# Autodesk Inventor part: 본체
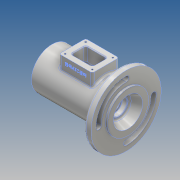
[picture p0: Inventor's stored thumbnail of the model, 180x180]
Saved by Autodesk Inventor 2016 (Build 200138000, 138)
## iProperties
Created: 2017-05
Part Number: 본체
Material: 알루미늄 6061
Document SubType Name: Modeling
Designer: Administrator
Density: 2.7 g/cm^3
Appearance: 알루미늄 - 평지
Mass: 677.521 g
Surface Area: 616.973 cm^2
Volume: 250.934 cm^3
Author: Administrator
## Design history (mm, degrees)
sketch "스케치2"
  geometry: L1 (-56, 0)-(59, 0); L2 (-56, 0)-(-56, 31); L3 (-56, 31)-(46, 31); L4 (46, 31)-(46, 53); L5 (46, 53)-(56, 53); L6 (56, 53)-(56, 31); L7 (56, 31)-(59, 31); L8 (59, 31)-(59, 0); 1 further point
  constraints: 16 end point, 5 perpendicular, 3 point on line, 1 horizontal, 1 vertical
  dimensions: "d1" = 115 distance of L1.start L1.end; "d2" = 3 distance between parallel lines of L6 L8; "d3" = 13 distance between parallel lines of L4 L8; "d4" = 106 diameter of L5 L1; "d5" = 62 diameter of L3 L1; "d6" = 56 distance from line of point (0, 0) L2
revolve "회전1" sketch "스케치2" stored, may be unused: angle "d7" = 90 deg
sketch "스케치3"
  geometry: L1 (-25, 20)-(25, 20); L2 (25, 20)-(25, -20); L3 (25, -20)-(-25, -20); L4 (-25, -20)-(-25, 20); L5 (-25, 20)-(25, -20); L6 (25, 20)-(-25, -20); 1 further point
  constraints: 12 end point, 2 midpoint, 2 parallel, 1 horizontal, 1 perpendicular
  dimensions: "d8" = 50 distance between parallel lines of L2 L4; "d9" = 40 distance between parallel lines of L3 L1
extrude "돌출1" join sketch "스케치3" distance "d10" = 44; taper "d11" = 0 deg
sketch "스케치5"
  geometry: L1 (-56, -31)-(-56, 31) reference; L2 (-56, 0)-(59, 0); L3 (59, -31)-(59, 31) reference; L4 (-56, 0)-(-56, 21); L5 (-56, 21)-(-47, 21); L6 (-47, 21)-(-47, 24); L7 (-47, 24)-(-44, 24); L8 (-44, 24)-(-44, 20); L9 (-44, 20)-(-35, 20); L10 (-35, 20)-(-35, 17.5); L11 (-35, 17.5)-(-31.75, 17.5); L12 (-31.75, 17.5)-(-31.75, 18.5); L13 (-31.75, 18.5)-(-30, 18.5); L14 (-30, 18.5)-(-30, 17.5); L15 (-30, 17.5)-(-19, 17.5); L16 (-19, 17.5)-(-19, 26); L17 (-19, 26)-(19, 26); L18 (19, 26)-(19, 17.5); L19 (19, 17.5)-(30, 17.5); L20 (30, 17.5)-(30, 16.5); L21 (30, 16.5)-(35, 16.5); L22 (35, 16.5)-(35, 10); L23 (35, 10)-(37.7, 10); L24 (37.7, 10)-(37.7, 12.5); L25 (37.7, 12.5)-(44.3, 12.5); L26 (46, -53)-(46, 53) reference; L27 (44.3, 12.5)-(45, 12.904); L28 (45, 12.904)-(45, 16); L29 (45, 16)-(59, 22); L30 (59, 22)-(59, 0); 2 further points
  constraints: 54 end point, 17 perpendicular, 4 point on line, 3 midpoint, 2 collinear, 2 vertical, 1 horizontal, 1 parallel, 1 vertical alignment
  dimensions: "d14" = 42 diameter of L5 L2; "d15" = 48 diameter of L7 L2; "d16" = 40 diameter of L9 L2; "d17" = 35 diameter of L11 L2; "d18" = 3 distance between parallel lines of L8 L6; "d19" = 12 distance between parallel lines of L8 L1; "d20" = 21 distance between parallel lines of L10 L1; "d21" = 37 diameter of L13 L2; "d22" = 1.75 distance from line of L14 L12.end; "d23" = 26 distance between parallel lines of L14 L4; "d24" = 11 distance between parallel lines of L16 L14; "d25" = 11 distance from line of L19.end L18; "d26" = 52 diameter of L17 L2; "d29" = 5 distance between parallel lines of L22 L20; "d31" = 2.7 distance between parallel lines of L24 L22; "d33" = 0.7 horizontal distance of L25.end L27.end; "d34" = 30 deg angle of L25 L27; "d35" = 14 distance from line of L29.end L28; "d36" = 44 diameter of L29.end L2; "d37" = 25 diameter of L25 L2; "d38" = 20 diameter of L23 L2; "d39" = 33 diameter of L21 L2; "d40" = 32 diameter of L28.end L2
revolve "회전2" sketch "스케치5" stored, may be unused: angle "d41" = 90 deg
sketch "스케치6"
  geometry: L1 (-16, 11)-(16, 11); L2 (16, 11)-(16, -11); L3 (16, -11)-(-16, -11); L4 (-16, -11)-(-16, 11); L5 (-16, 11)-(16, -11); L6 (16, 11)-(-16, -11); 1 further point
  constraints: 12 end point, 2 midpoint, 2 parallel, 1 horizontal, 1 perpendicular
  dimensions: "d42" = 32 distance of L2.end L3.end; "d43" = 22 distance of L1.end L2.end
extrude "돌출2" cut sketch "스케치6" stored distance "d44" = 44; taper "d45" = 0 deg; dims "d8" = 50, "d9" = 40
sketch "스케치7"
  geometry: L1 (25, 20)-(-25, 20) reference; L2 (-25, 20)-(-25, -20) reference; L3 (-25, -20)-(25, -20) reference; L4 (25, -20)-(25, 20) reference; L5 (0, 20)-(0, -20); L6 (-25, 0)-(25, 0); 5 further points
  constraints: 4 end point, 4 midpoint, 2 horizontal alignment, 2 symmetric about line, 2 vertical alignment
  dimensions: "d46" = 31 distance of point (-20.5, -15.5) point (-20.5, 15.5); "d47" = 41 distance of point (20.5, 15.5) point (-20.5, 15.5)
hole "구멍1" sketch "스케치7" at (-20.5, 15.5), (-20.5, -15.5), (20.5, -15.5), (20.5, 15.5) diameter "d48" = 2.459; stored, may be unused: countersink angle "d52" = 90 deg, drill point angle "d54" = 118 deg; dims "d49" = 6, "d50" = 4, "d51" = 2, "d53" = 8
sketch "스케치8"
  geometry: L1 (0, -45.5)-(0, 45.5); L2 (-45.5, 0.144)-(45.5, 0.144); C1 r 31 at (0, 0) reference; A1 r 4 centre (0, -41.5) between (0, -45.5) and (0, -37.5); A2 r 4 centre (-41.5, 0.144) between (-37.5, 0.134) and (-45.5, 0.144); A3 r 4 centre (0, 41.5) between (0, 45.5) and (0, 37.5); A4 r 4 centre (41.5, 0.144) between (37.5, 0.131) and (45.5, 0.144); A5 r 37.5 centre (0, 0) between (-37.5, 0.134) and (0, -37.5); A6 r 37.5 centre (0, 0) between (37.5, 0.131) and (0, 37.5); A7 r 45.5 centre (0, 0) between (-45.5, 0.144) and (0, -45.5); A8 r 45.5 centre (0, 0) between (45.5, 0.144) and (0, 45.5)
  constraints: 17 point on circle, 8 centre point, 4 end point, 4 point on line, 3 equal radius, 2 coincident, 1 horizontal
  dimensions: "d57" = 37.5 radius of A6; "d58" = 37.5 radius of A5; "d59" = 45.5 radius of A7; "d60" = 45.5 radius of A8; "d61" = 4 radius of A3
extrude "돌출3" cut sketch "스케치8" stored distance "d62" = 44; taper "d63" = 0 deg
chamfer "모따기1" distance "d64" = 1; stored, may be unused: second distance "d65" = 2, angle "d66" = 45 deg
fillet "모깎기1" dims "d67" = 3
fillet "모깎기2" dims "d68" = 0.3
sketch "스케치9"
  geometry: L1 (0, 20.315)-(50, 20.315) reference; L2 (-31, -54.685)-(-31, 7.315) reference; 2 further points
  constraints: 1 other
  dimensions: "d69" = 8 distance from line of point (25, 12.315) L1; "d70" = 56 distance from line of point (25, 12.315) L2
feature "엠보싱1" sketch "스케치9" dims "d1" = 115, "d2" = 3, "d3" = 13, "d4" = 106, "d5" = 62, "d6" = 56, "d71" = 0.5, "d72" = 0
fillet "모깎기3" dims "d73" = 3
fillet "모깎기4" dims "d74" = 3
chamfer "모따기2" distance "d75" = 1; stored, may be unused: second distance "d76" = 2, angle "d77" = 45 deg
feature "스레드1" dims "d78" = 10, "d79" = 0
chamfer "모따기3" distance "d80" = 1; stored, may be unused: second distance "d81" = 2, angle "d82" = 45 deg
node "솔리드1"
other parameters: "d55" = 91, "d56" = 75
